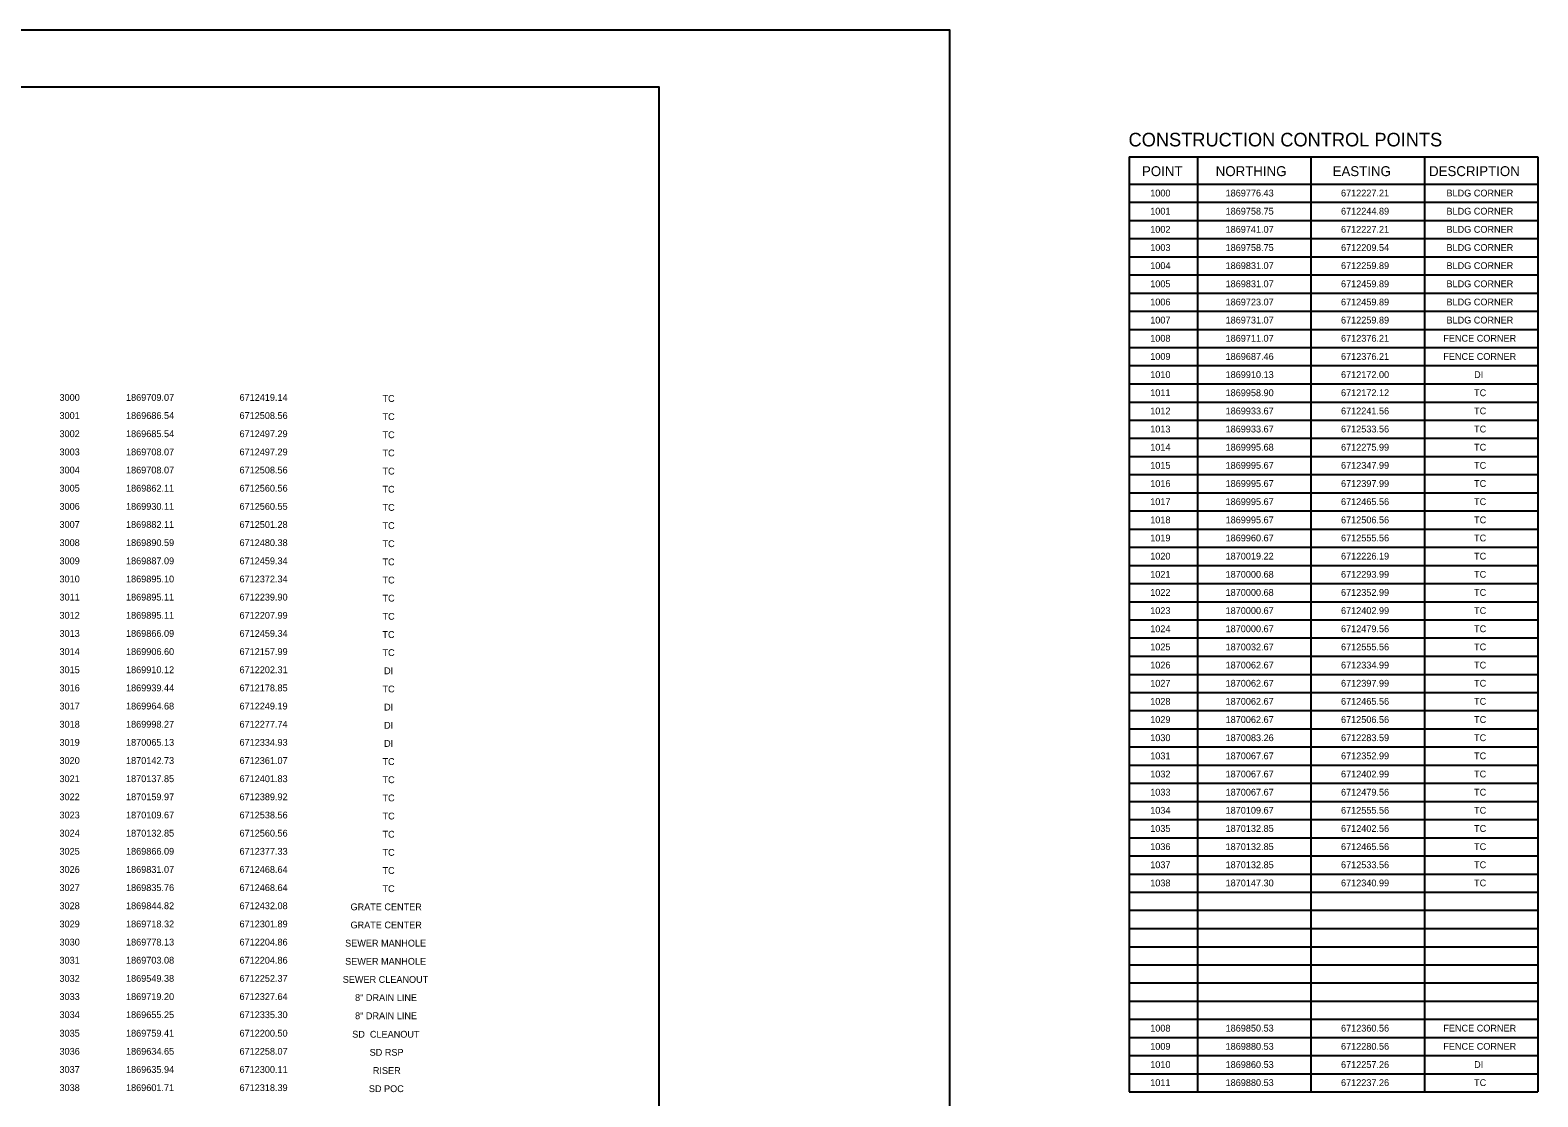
# Model space of a CAD drawing. Extents: x 0 to 4.36, y 0 to 2.5.
# Drawn here: x 2.15 to 4.364, y 0.933 to 2.5 of the extents above; entities that cross this region are included whole.
import ezdxf

# ---------------------------------------------------------------- set-up
doc = ezdxf.new("R2010")
doc.units = 0
for name, color, linetype in [('C-TEXT', 7, 'Continuous'), ('G-TTLB-OTLN', 7, 'Continuous'), ('G-TTLB-VIEW', 7, 'Continuous'), ('Nongeo Data(60)', 7, 'Continuous')]:
    doc.layers.add(name, color=color, linetype=linetype)

msp = doc.modelspace()

# ---------------------------------------------------------------- linework, layer by layer
at = {"layer": 'G-TTLB-OTLN'}
msp.add_lwpolyline([(0, 0), (3.5, 0), (3.5, 2.5), (0, 2.5)], close=True, dxfattribs=at)
at = {"layer": 'G-TTLB-VIEW'}
msp.add_lwpolyline([(0.1667, 2.4167), (3.0729, 2.4167), (3.0729, 0.0833), (0.1667, 0.0833)], close=True, dxfattribs=at)
at = {"layer": 'Nongeo Data(60)'}
for p, q in [((3.7638, 2.3138), (4.3638, 2.3138)), ((3.7638, 2.3138), (3.7638, 0.9405)), ((3.8638, 2.3138), (3.8638, 0.9405)), ((4.0305, 2.3138), (4.0305, 0.9405)), ((4.1971, 2.3138), (4.1971, 0.9405)), ((4.3638, 2.3138), (4.3638, 0.9405)), ((3.7638, 2.2738), (4.3638, 2.2738)), ((3.7638, 2.2472), (4.3638, 2.2472)), ((3.7638, 2.2205), (4.3638, 2.2205)), ((3.7638, 2.1938), (4.3638, 2.1938)), ((3.7638, 2.1672), (4.3638, 2.1672)), ((3.7638, 2.1405), (4.3638, 2.1405)), ((3.7638, 2.1138), (4.3638, 2.1138)), ((3.7638, 2.0872), (4.3638, 2.0872)), ((3.7638, 2.0605), (4.3638, 2.0605)), ((3.7638, 2.0338), (4.3638, 2.0338)), ((3.7638, 2.0072), (4.3638, 2.0072)), ((3.7638, 1.9805), (4.3638, 1.9805)), ((3.7638, 1.9538), (4.3638, 1.9538)), ((3.7638, 1.9272), (4.3638, 1.9272)), ((3.7638, 1.9005), (4.3638, 1.9005)), ((3.7638, 1.8738), (4.3638, 1.8738)), ((3.7638, 1.8472), (4.3638, 1.8472)), ((3.7638, 1.8205), (4.3638, 1.8205)), ((3.7638, 1.7938), (4.3638, 1.7938)), ((3.7638, 1.7672), (4.3638, 1.7672)), ((3.7638, 1.7405), (4.3638, 1.7405)), ((3.7638, 1.7138), (4.3638, 1.7138)), ((3.7638, 1.6872), (4.3638, 1.6872)), ((3.7638, 1.6605), (4.3638, 1.6605)), ((3.7638, 1.6338), (4.3638, 1.6338)), ((3.7638, 1.6072), (4.3638, 1.6072)), ((3.7638, 1.5805), (4.3638, 1.5805)), ((3.7638, 1.5538), (4.3638, 1.5538)), ((3.7638, 1.5272), (4.3638, 1.5272)), ((3.7638, 1.5005), (4.3638, 1.5005)), ((3.7638, 1.4738), (4.3638, 1.4738)), ((3.7638, 1.4472), (4.3638, 1.4472)), ((3.7638, 1.4205), (4.3638, 1.4205)), ((3.7638, 1.3938), (4.3638, 1.3938)), ((3.7638, 1.3672), (4.3638, 1.3672)), ((3.7638, 1.3405), (4.3638, 1.3405)), ((3.7638, 1.3138), (4.3638, 1.3138)), ((3.7638, 1.2872), (4.3638, 1.2872)), ((3.7638, 1.2605), (4.3638, 1.2605)), ((3.7638, 1.2338), (4.3638, 1.2338)), ((3.7638, 1.2072), (4.3638, 1.2072)), ((3.7638, 1.1805), (4.3638, 1.1805)), ((3.7638, 1.1538), (4.3638, 1.1538)), ((3.7638, 1.1272), (4.3638, 1.1272)), ((3.7638, 1.1005), (4.3638, 1.1005)), ((3.7638, 1.0738), (4.3638, 1.0738)), ((3.7638, 1.0472), (4.3638, 1.0472)), ((3.7638, 1.0205), (4.3638, 1.0205)), ((3.7638, 0.9938), (4.3638, 0.9938)), ((3.7638, 0.9672), (4.3638, 0.9672)), ((3.7638, 0.9405), (4.3638, 0.9405))]:
    msp.add_line(p, q, dxfattribs=at)

# ---------------------------------------------------------------- texts
at = {"layer": 'C-TEXT'}
for s, p in [('1000', (3.7945, 2.2557)), ('1869776.43', (3.9052, 2.2557)), ('6712227.21', (4.0747, 2.2557)), ('BLDG CORNER', (4.2296, 2.2557)), ('1001', (3.7945, 2.2291)), ('1869758.75', (3.9052, 2.2291)), ('6712244.89', (4.0747, 2.2291)), ('BLDG CORNER', (4.2296, 2.2291)), ('1002', (3.7945, 2.2024)), ('1869741.07', (3.9052, 2.2024)), ('6712227.21', (4.0747, 2.2024)), ('BLDG CORNER', (4.2296, 2.2024)), ('1003', (3.7945, 2.1757)), ('1869758.75', (3.9052, 2.1757)), ('6712209.54', (4.0747, 2.1757)), ('BLDG CORNER', (4.2296, 2.1757)), ('1004', (3.7945, 2.1491)), ('1869831.07', (3.9052, 2.1491)), ('6712259.89', (4.0747, 2.1491)), ('BLDG CORNER', (4.2296, 2.1491)), ('1005', (3.7945, 2.1224)), ('1869831.07', (3.9052, 2.1224)), ('6712459.89', (4.0747, 2.1224)), ('BLDG CORNER', (4.2296, 2.1224)), ('1006', (3.7945, 2.0957)), ('1869723.07', (3.9052, 2.0957)), ('6712459.89', (4.0747, 2.0957)), ('BLDG CORNER', (4.2296, 2.0957)), ('1007', (3.7945, 2.0691)), ('1869731.07', (3.9052, 2.0691)), ('6712259.89', (4.0747, 2.0691)), ('BLDG CORNER', (4.2296, 2.0691)), ('1008', (3.7945, 2.0424)), ('1869711.07', (3.9052, 2.0424)), ('6712376.21', (4.0747, 2.0424)), ('FENCE CORNER', (4.225, 2.0424)), ('1009', (3.7945, 2.0157)), ('1869687.46', (3.9052, 2.0157)), ('6712376.21', (4.0747, 2.0157)), ('FENCE CORNER', (4.225, 2.0157)), ('1010', (3.7945, 1.9891)), ('1869910.13', (3.9052, 1.9891)), ('6712172.00', (4.0747, 1.9891)), ('DI', (4.2702, 1.9891)), ('1011', (3.7945, 1.9624)), ('1869958.90', (3.9052, 1.9624)), ('6712172.12', (4.0747, 1.9624)), ('TC', (4.2702, 1.9624)), ('3000', (2.1926, 1.9555)), ('1869709.07', (2.2903, 1.9555)), ('6712419.14', (2.457, 1.9555)), ('TC', (2.667, 1.954)), ('3001', (2.1926, 1.9289)), ('1869686.54', (2.2903, 1.9289)), ('6712508.56', (2.457, 1.9289)), ('TC', (2.667, 1.9273)), ('1012', (3.7945, 1.9357)), ('1869933.67', (3.9052, 1.9357)), ('6712241.56', (4.0747, 1.9357)), ('TC', (4.2702, 1.9357)), ('3002', (2.1926, 1.9022)), ('1869685.54', (2.2903, 1.9022)), ('6712497.29', (2.457, 1.9022)), ('TC', (2.667, 1.9007)), ('1013', (3.7945, 1.9091)), ('1869933.67', (3.9052, 1.9091)), ('6712533.56', (4.0747, 1.9091)), ('TC', (4.2702, 1.9091)), ('3003', (2.1926, 1.8755)), ('1869708.07', (2.2903, 1.8755)), ('6712497.29', (2.457, 1.8755)), ('TC', (2.667, 1.874)), ('1014', (3.7945, 1.8824)), ('1869995.68', (3.9052, 1.8824)), ('6712275.99', (4.0747, 1.8824)), ('TC', (4.2702, 1.8824)), ('1015', (3.7945, 1.8557)), ('1869995.67', (3.9052, 1.8557)), ('6712347.99', (4.0747, 1.8557)), ('TC', (4.2702, 1.8557)), ('3004', (2.1926, 1.8489)), ('1869708.07', (2.2903, 1.8489)), ('6712508.56', (2.457, 1.8489)), ('TC', (2.667, 1.8473)), ('1016', (3.7945, 1.8291)), ('1869995.67', (3.9052, 1.8291)), ('6712397.99', (4.0747, 1.8291)), ('TC', (4.2702, 1.8291)), ('3005', (2.1926, 1.8222)), ('1869862.11', (2.2903, 1.8222)), ('6712560.56', (2.457, 1.8222)), ('TC', (2.667, 1.8207)), ('3006', (2.1926, 1.7955)), ('1869930.11', (2.2903, 1.7955)), ('6712560.55', (2.457, 1.7955)), ('TC', (2.667, 1.794)), ('1017', (3.7945, 1.8024)), ('1869995.67', (3.9052, 1.8024)), ('6712465.56', (4.0747, 1.8024)), ('TC', (4.2702, 1.8024)), ('3007', (2.1926, 1.7689)), ('1869882.11', (2.2903, 1.7689)), ('6712501.28', (2.457, 1.7689)), ('TC', (2.667, 1.7673)), ('1018', (3.7945, 1.7757)), ('1869995.67', (3.9052, 1.7757)), ('6712506.56', (4.0747, 1.7757)), ('TC', (4.2702, 1.7757)), ('3008', (2.1926, 1.7422)), ('1869890.59', (2.2903, 1.7422)), ('6712480.38', (2.457, 1.7422)), ('TC', (2.667, 1.7407)), ('1019', (3.7945, 1.7491)), ('1869960.67', (3.9052, 1.7491)), ('6712555.56', (4.0747, 1.7491)), ('TC', (4.2702, 1.7491)), ('1020', (3.7945, 1.7224)), ('1870019.22', (3.9052, 1.7224)), ('6712226.19', (4.0747, 1.7224)), ('TC', (4.2702, 1.7224)), ('3009', (2.1926, 1.7155)), ('1869887.09', (2.2903, 1.7155)), ('6712459.34', (2.457, 1.7155)), ('TC', (2.667, 1.714)), ('1021', (3.7945, 1.6957)), ('1870000.68', (3.9052, 1.6957)), ('6712293.99', (4.0747, 1.6957)), ('TC', (4.2702, 1.6957)), ('3010', (2.1926, 1.6889)), ('1869895.10', (2.2903, 1.6889)), ('6712372.34', (2.457, 1.6889)), ('TC', (2.667, 1.6873)), ('3011', (2.1926, 1.6622)), ('1869895.11', (2.2903, 1.6622)), ('6712239.90', (2.457, 1.6622)), ('TC', (2.667, 1.6607)), ('1022', (3.7945, 1.6691)), ('1870000.68', (3.9052, 1.6691)), ('6712352.99', (4.0747, 1.6691)), ('TC', (4.2702, 1.6691)), ('3012', (2.1926, 1.6355)), ('1869895.11', (2.2903, 1.6355)), ('6712207.99', (2.457, 1.6355)), ('TC', (2.667, 1.634)), ('1023', (3.7945, 1.6424)), ('1870000.67', (3.9052, 1.6424)), ('6712402.99', (4.0747, 1.6424)), ('TC', (4.2702, 1.6424)), ('3013', (2.1926, 1.6089)), ('1869866.09', (2.2903, 1.6089)), ('6712459.34', (2.457, 1.6089)), ('TC', (2.6669, 1.6073)), ('1024', (3.7945, 1.6157)), ('1870000.67', (3.9052, 1.6157)), ('6712479.56', (4.0747, 1.6157)), ('TC', (4.2702, 1.6157)), ('1025', (3.7945, 1.5891)), ('1870032.67', (3.9052, 1.5891)), ('6712555.56', (4.0747, 1.5891)), ('TC', (4.2702, 1.5891)), ('3014', (2.1926, 1.5822)), ('1869906.60', (2.2903, 1.5822)), ('6712157.99', (2.457, 1.5822)), ('TC', (2.667, 1.5807)), ('1026', (3.7945, 1.5624)), ('1870062.67', (3.9052, 1.5624)), ('6712334.99', (4.0747, 1.5624)), ('TC', (4.2702, 1.5624)), ('3015', (2.1926, 1.5555)), ('1869910.12', (2.2903, 1.5555)), ('6712202.31', (2.457, 1.5555)), ('DI', (2.6693, 1.554)), ('3016', (2.1926, 1.5289)), ('1869939.44', (2.2903, 1.5289)), ('6712178.85', (2.457, 1.5289)), ('TC', (2.667, 1.5273)), ('1027', (3.7945, 1.5357)), ('1870062.67', (3.9052, 1.5357)), ('6712397.99', (4.0747, 1.5357)), ('TC', (4.2702, 1.5357)), ('3017', (2.1926, 1.5022)), ('1869964.68', (2.2903, 1.5022)), ('6712249.19', (2.457, 1.5022)), ('DI', (2.6693, 1.5007)), ('1028', (3.7945, 1.5091)), ('1870062.67', (3.9052, 1.5091)), ('6712465.56', (4.0747, 1.5091)), ('TC', (4.2702, 1.5091)), ('3018', (2.1926, 1.4755)), ('1869998.27', (2.2903, 1.4755)), ('6712277.74', (2.457, 1.4755)), ('DI', (2.6693, 1.474)), ('1029', (3.7945, 1.4824)), ('1870062.67', (3.9052, 1.4824)), ('6712506.56', (4.0747, 1.4824)), ('TC', (4.2702, 1.4824)), ('1030', (3.7945, 1.4557)), ('1870083.26', (3.9052, 1.4557)), ('6712283.59', (4.0747, 1.4557)), ('TC', (4.2702, 1.4557)), ('3019', (2.1926, 1.4489)), ('1870065.13', (2.2903, 1.4489)), ('6712334.93', (2.457, 1.4489)), ('DI', (2.6693, 1.4473)), ('3020', (2.1926, 1.4222)), ('1870142.73', (2.2903, 1.4222)), ('6712361.07', (2.457, 1.4222)), ('TC', (2.667, 1.4207)), ('1031', (3.7945, 1.4291)), ('1870067.67', (3.9052, 1.4291)), ('6712352.99', (4.0747, 1.4291)), ('TC', (4.2702, 1.4291)), ('3021', (2.1926, 1.3955)), ('1870137.85', (2.2903, 1.3955)), ('6712401.83', (2.457, 1.3955)), ('TC', (2.667, 1.394)), ('1032', (3.7945, 1.4024)), ('1870067.67', (3.9052, 1.4024)), ('6712402.99', (4.0747, 1.4024)), ('TC', (4.2702, 1.4024)), ('3022', (2.1926, 1.3689)), ('1870159.97', (2.2903, 1.3689)), ('6712389.92', (2.457, 1.3689)), ('TC', (2.667, 1.3673)), ('1033', (3.7945, 1.3757)), ('1870067.67', (3.9052, 1.3757)), ('6712479.56', (4.0747, 1.3757)), ('TC', (4.2702, 1.3757)), ('3023', (2.1926, 1.3422)), ('1870109.67', (2.2903, 1.3422)), ('6712538.56', (2.457, 1.3422)), ('TC', (2.667, 1.3407)), ('1034', (3.7945, 1.3491)), ('1870109.67', (3.9052, 1.3491)), ('6712555.56', (4.0747, 1.3491)), ('TC', (4.2702, 1.3491)), ('1035', (3.7945, 1.3224)), ('1870132.85', (3.9052, 1.3224)), ('6712402.56', (4.0747, 1.3224)), ('TC', (4.2702, 1.3224)), ('3024', (2.1926, 1.3155)), ('1870132.85', (2.2903, 1.3155)), ('6712560.56', (2.457, 1.3155)), ('TC', (2.667, 1.314)), ('3025', (2.1926, 1.2889)), ('1869866.09', (2.2903, 1.2889)), ('6712377.33', (2.457, 1.2889)), ('TC', (2.667, 1.2873)), ('1036', (3.7945, 1.2957)), ('1870132.85', (3.9052, 1.2957)), ('6712465.56', (4.0747, 1.2957)), ('TC', (4.2702, 1.2957)), ('3026', (2.1926, 1.2622)), ('1869831.07', (2.2903, 1.2622)), ('6712468.64', (2.457, 1.2622)), ('TC', (2.667, 1.2607)), ('1037', (3.7945, 1.2691)), ('1870132.85', (3.9052, 1.2691)), ('6712533.56', (4.0747, 1.2691)), ('TC', (4.2702, 1.2691)), ('3027', (2.1926, 1.2355)), ('1869835.76', (2.2903, 1.2355)), ('6712468.64', (2.457, 1.2355)), ('TC', (2.667, 1.234)), ('1038', (3.7945, 1.2424)), ('1870147.30', (3.9052, 1.2424)), ('6712340.99', (4.0747, 1.2424)), ('TC', (4.2702, 1.2424)), ('3028', (2.1926, 1.2089)), ('1869844.82', (2.2903, 1.2089)), ('6712432.08', (2.457, 1.2089)), ('GRATE CENTER', (2.62, 1.2073)), ('3029', (2.1926, 1.1822)), ('1869718.32', (2.2903, 1.1822)), ('6712301.89', (2.457, 1.1822)), ('GRATE CENTER', (2.62, 1.1807)), ('3030', (2.1926, 1.1555)), ('1869778.13', (2.2903, 1.1555)), ('6712204.86', (2.457, 1.1555)), ('SEWER MANHOLE', (2.6121, 1.154)), ('3031', (2.1926, 1.1289)), ('1869703.08', (2.2903, 1.1289)), ('6712204.86', (2.457, 1.1289)), ('SEWER MANHOLE', (2.6121, 1.1273)), ('3032', (2.1926, 1.1022)), ('1869549.38', (2.2903, 1.1022)), ('6712252.37', (2.457, 1.1022)), ('SEWER CLEANOUT', (2.6086, 1.1007)), ('3033', (2.1926, 1.0755)), ('1869719.20', (2.2903, 1.0755)), ('6712327.64', (2.457, 1.0755)), ('8" DRAIN LINE', (2.6267, 1.074)), ('3034', (2.1926, 1.0489)), ('1869655.25', (2.2903, 1.0489)), ('6712335.30', (2.457, 1.0489)), ('8" DRAIN LINE', (2.6267, 1.0473)), ('3035', (2.1926, 1.0217)), ('1869759.41', (2.2903, 1.0217)), ('6712200.50', (2.457, 1.0217)), ('SD  CLEANOUT', (2.6225, 1.0202)), ('1008', (3.7945, 1.0291)), ('1869850.53', (3.9052, 1.0291)), ('6712360.56', (4.0747, 1.0291)), ('FENCE CORNER', (4.225, 1.0291)), ('3036', (2.1926, 0.9951)), ('1869634.65', (2.2903, 0.9951)), ('6712258.07', (2.457, 0.9951)), ('SD RSP', (2.6481, 0.9936)), ('1009', (3.7945, 1.0024)), ('1869880.53', (3.9052, 1.0024)), ('6712280.56', (4.0747, 1.0024)), ('FENCE CORNER', (4.225, 1.0024)), ('3037', (2.1926, 0.9684)), ('1869635.94', (2.2903, 0.9684)), ('6712300.11', (2.457, 0.9684)), ('RISER', (2.6528, 0.9669)), ('1010', (3.7945, 0.9757)), ('1869860.53', (3.9052, 0.9757)), ('6712257.26', (4.0747, 0.9757)), ('DI', (4.2702, 0.9757)), ('1011', (3.7945, 0.9491)), ('1869880.53', (3.9052, 0.9491)), ('6712237.26', (4.0747, 0.9491)), ('TC', (4.2702, 0.9491)), ('3038', (2.1926, 0.9417)), ('1869601.71', (2.2903, 0.9417)), ('6712318.39', (2.457, 0.9417)), ('SD POC', (2.647, 0.9402))]:
    msp.add_text(s, height=0.01, dxfattribs=at).set_placement(p)
at = {"layer": 'Nongeo Data(60)'}
for s, height, p in [('CONSTRUCTION CONTROL POINTS', 0.02, (3.7627, 2.3292)), ('POINT', 0.01458, (3.7824, 2.2856)), ('NORTHING', 0.01458, (3.8907, 2.2856)), ('EASTING', 0.01458, (4.0624, 2.2856)), ('DESCRIPTION', 0.014583, (4.204, 2.2856))]:
    msp.add_text(s, height=height, dxfattribs=at).set_placement(p)

doc.saveas('drawing.dxf')
